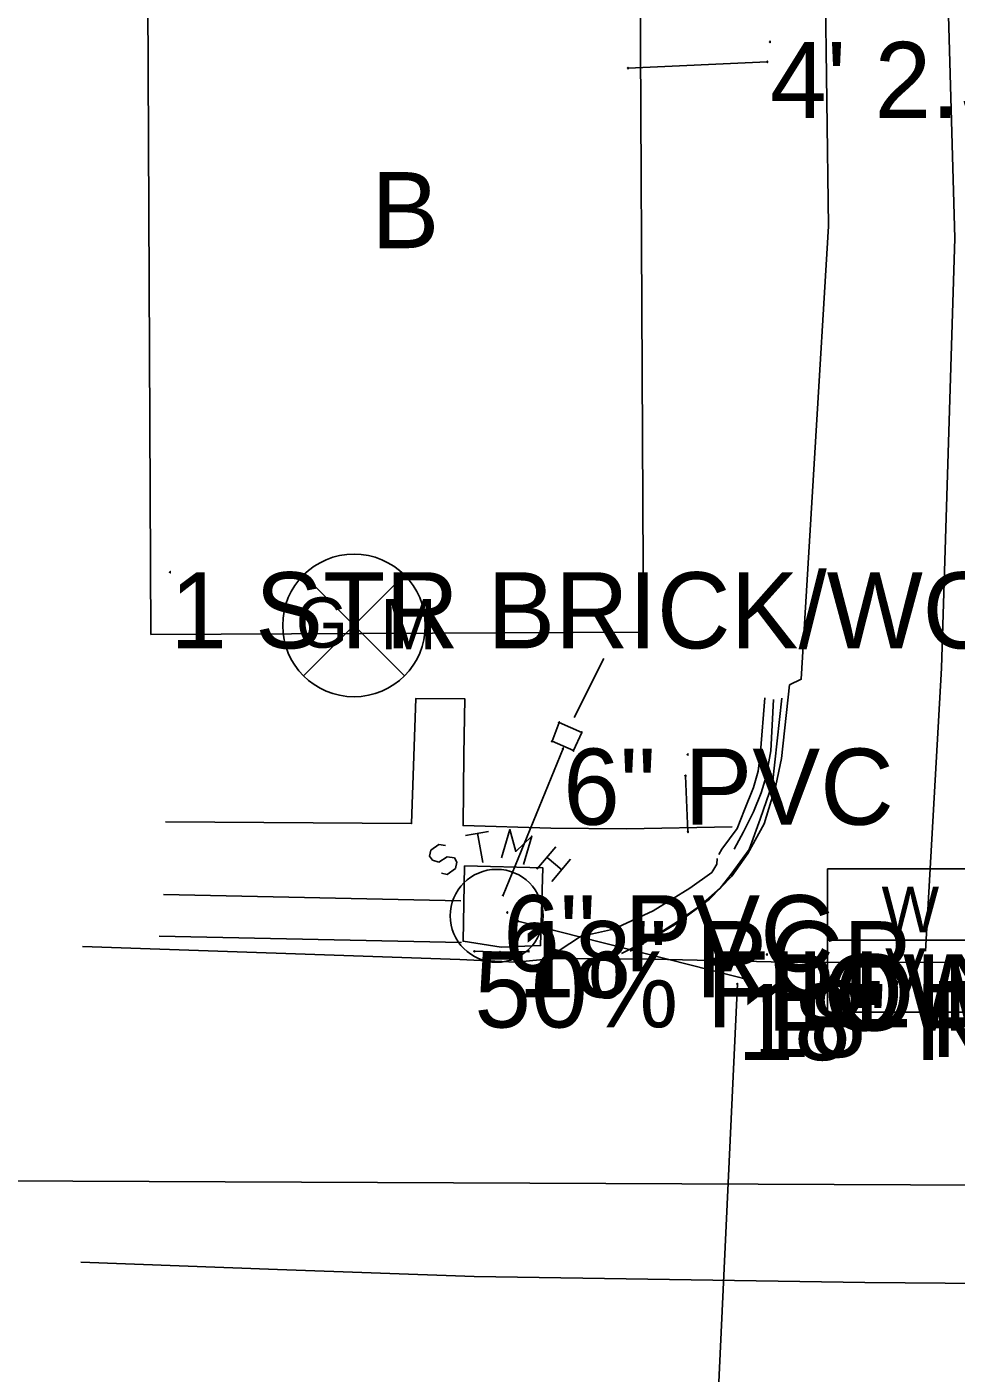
# Model space of a CAD drawing. Extents: x 1304270 to 1306561, y 1876019 to 1876752.
# Drawn here: x 1304916.1 to 1304977.1, y 1876403.7 to 1876492.1 of the extents above; entities that cross this region are included whole.
import ezdxf

# ---------------------------------------------------------------- set-up
doc = ezdxf.new("R2010")
doc.units = 0
for name, color, linetype in [('S_BUILDING', 7, 'Continuous'), ('S_BUILDING_ANNOT', 7, 'Continuous'), ('S_CATCH_BASIN', 7, 'Continuous'), ('S_CATCH_BASIN_ANNOT', 7, 'Continuous'), ('S_CURB', 7, 'Continuous'), ('S_DITCHLINE', 7, 'Continuous'), ('S_DRG_PT_SYM', 7, 'Continuous'), ('S_DROP_INLET', 7, 'Continuous'), ('S_EDGE_CONCRETE', 7, 'Continuous'), ('S_EDGE_PAVEMENT', 7, 'Continuous'), ('S_ELECTRIC_UTILITIES_ANNOT', 7, 'Continuous'), ('S_FENCE', 7, 'Continuous'), ('S_GAS_UTILITIES', 7, 'Continuous'), ('S_GATE_ANNOT', 7, 'Continuous'), ('S_MSC_PT_SYM', 7, 'Continuous'), ('S_PAVEMENT_CROWN', 7, 'Continuous'), ('S_SANITARY_SEWER', 7, 'Continuous'), ('S_SIDEWALK', 7, 'Continuous'), ('S_STORM_SEWER', 7, 'Continuous'), ('S_STORM_SEWER_ANNOT', 7, 'Continuous'), ('S_STR_PT_SYM', 7, 'Continuous'), ('S_SURVEY_TEXT_ANNOT', 7, 'Continuous'), ('S_UTL_PT_SYM', 7, 'Continuous'), ('S_WATER_UTILITIES', 7, 'Continuous')]:
    doc.layers.add(name, color=color, linetype=linetype)

msp = doc.modelspace()

# ---------------------------------------------------------------- linework, layer by layer
at = {"layer": 'S_BUILDING'}
msp.add_lwpolyline([(1304923.987, 1876507.767), (1304924.258, 1876452.214), (1304956.586, 1876452.372), (1304956.315, 1876507.925)], close=True, dxfattribs=at)
at = {"layer": 'S_CATCH_BASIN'}
for p, q in [((1304945.492, 1876431.412), (1304947.184, 1876431.359)), ((1304947.184, 1876431.359), (1304949.069, 1876431.41))]:
    msp.add_line(p, q, dxfattribs=at)
at = {"layer": 'S_CURB'}
for points in [[(1304964.549, 1876448.045), (1304964.28, 1876444.515), (1304964.13, 1876443.245), (1304963.818, 1876442.168), (1304963.225, 1876440.694), (1304962.732, 1876439.484), (1304961.738, 1876438.127), (1304961.546, 1876437.769)], [(1304924.805, 1876432.411), (1304944.655, 1876431.983)]]:
    msp.add_lwpolyline(points, dxfattribs=at)
at = {"layer": 'S_DITCHLINE'}
msp.add_lwpolyline([(1304953.99, 1876450.633), (1304952.041, 1876446.752)], dxfattribs=at)
at = {"layer": 'S_DRG_PT_SYM'}
for points in [[(1304951.062, 1876446.43), (1304951.062, 1876446.48), (1304951.062, 1876446.43), (1304951.012, 1876446.43), (1304951.062, 1876446.43), (1304951.062, 1876446.38), (1304951.062, 1876446.43), (1304951.112, 1876446.43)], [(1304952.536, 1876445.782), (1304952.536, 1876445.832), (1304952.536, 1876445.782), (1304952.486, 1876445.782), (1304952.536, 1876445.782), (1304952.536, 1876445.732), (1304952.536, 1876445.782), (1304952.586, 1876445.782)], [(1304950.595, 1876445.206), (1304950.595, 1876445.256), (1304950.595, 1876445.206), (1304950.545, 1876445.206), (1304950.595, 1876445.206), (1304950.595, 1876445.156), (1304950.595, 1876445.206), (1304950.645, 1876445.206)], [(1304952, 1876444.592), (1304952, 1876444.642), (1304952, 1876444.592), (1304951.95, 1876444.592), (1304952, 1876444.592), (1304952, 1876444.542), (1304952, 1876444.592), (1304952.05, 1876444.592)], [(1304945.492, 1876431.412), (1304945.492, 1876431.462), (1304945.492, 1876431.412), (1304945.442, 1876431.412), (1304945.492, 1876431.412), (1304945.492, 1876431.362), (1304945.492, 1876431.412), (1304945.542, 1876431.412)], [(1304947.184, 1876431.359), (1304947.184, 1876431.409), (1304947.184, 1876431.359), (1304947.134, 1876431.359), (1304947.184, 1876431.359), (1304947.184, 1876431.309), (1304947.184, 1876431.359), (1304947.234, 1876431.359)], [(1304949.069, 1876431.41), (1304949.069, 1876431.46), (1304949.069, 1876431.41), (1304949.019, 1876431.41), (1304949.069, 1876431.41), (1304949.069, 1876431.36), (1304949.069, 1876431.41), (1304949.12, 1876431.41)]]:
    msp.add_lwpolyline(points, dxfattribs=at)
at = {"layer": 'S_DROP_INLET'}
for p, q in [((1304951.062, 1876446.43), (1304950.595, 1876445.206)), ((1304952.536, 1876445.782), (1304951.062, 1876446.43)), ((1304952, 1876444.592), (1304952.536, 1876445.782)), ((1304950.595, 1876445.206), (1304952, 1876444.592))]:
    msp.add_line(p, q, dxfattribs=at)
at = {"layer": 'S_EDGE_CONCRETE'}
for points in [[(1304955.143, 1876431.273), (1304956.833, 1876432.108), (1304958.801, 1876433.34), (1304960.333, 1876434.411), (1304961.624, 1876435.566), (1304962.341, 1876436.47), (1304963.53, 1876438.087), (1304964.251, 1876440.084), (1304965.054, 1876442.428), (1304965.678, 1876448.024)], [(1304965.133, 1876447.94), (1304964.944, 1876444.58), (1304964.654, 1876442.88), (1304964.312, 1876441.821), (1304963.818, 1876440.561), (1304963.168, 1876439.246), (1304962.554, 1876438.126)], [(1304950.145, 1876431.662), (1304951.062, 1876431.474), (1304952.463, 1876432.387), (1304954.621, 1876432.867), (1304957.234, 1876434.071), (1304959.631, 1876435.549), (1304961.069, 1876436.579), (1304961.406, 1876437.144), (1304961.436, 1876437.506)]]:
    msp.add_lwpolyline(points, dxfattribs=at)
msp.add_lwpolyline([(1304944.837, 1876437.016), (1304944.749, 1876432.074), (1304947.254, 1876431.687), (1304949.84, 1876431.794), (1304949.981, 1876436.893)], close=True, dxfattribs=at)
at = {"layer": 'S_EDGE_PAVEMENT'}
for points in [[(1304955.711, 1876431.426), (1304958.857, 1876433.289), (1304960.923, 1876434.833), (1304962.396, 1876436.344), (1304963.446, 1876437.843), (1304964.523, 1876439.777), (1304965.284, 1876442.294), (1304965.646, 1876444.073), (1304966.18, 1876448.895), (1304966.95, 1876449.268), (1304967.839, 1876464.146), (1304968.728, 1876479.025), (1304968.524, 1876495.495), (1304968.319, 1876511.966), (1304968.15, 1876529.158), (1304967.981, 1876546.351), (1304968.71, 1876560.16), (1304968.788, 1876563.104)], [(1304919.779, 1876431.718), (1304944.538, 1876430.873), (1304948.222, 1876430.692), (1304950.692, 1876430.942), (1304957.212, 1876430.901), (1304966.928, 1876430.679), (1304977.139, 1876430.697), (1304984.136, 1876430.53), (1304987.418, 1876428.94), (1304989.146, 1876428.281), (1304990.755, 1876427.243), (1304997.978, 1876427.391), (1305006.508, 1876426.141), (1305007.367, 1876424.801), (1305008.544, 1876424.166), (1305009.948, 1876424.231), (1305012.143, 1876425.041), (1305027.35, 1876425.193), (1305037.635, 1876424.503)]]:
    msp.add_lwpolyline(points, dxfattribs=at)
at = {"layer": 'S_FENCE'}
msp.add_line((1304964.719, 1876489.804), (1304955.583, 1876489.39), dxfattribs=at)
msp.add_lwpolyline([(1304964.719, 1876489.804), (1304955.583, 1876489.39)], dxfattribs=at)
msp.add_lwpolyline([(1304964.719, 1876489.804), (1304955.583, 1876489.39)], dxfattribs=at)
at = {"layer": 'S_GAS_UTILITIES'}
for p, q in [((1304934.282, 1876449.497), (1304940.901, 1876456.116)), ((1304934.282, 1876456.116), (1304940.901, 1876449.497))]:
    msp.add_line(p, q, dxfattribs=at)
msp.add_circle((1304937.591, 1876452.806), 4.681, dxfattribs=at)
at = {"layer": 'S_MSC_PT_SYM'}
for points in [[(1304964.907, 1876491.11), (1304964.907, 1876491.16), (1304964.907, 1876491.11), (1304964.857, 1876491.11), (1304964.907, 1876491.11), (1304964.907, 1876491.06), (1304964.907, 1876491.11), (1304964.957, 1876491.11)], [(1304964.719, 1876489.804), (1304964.719, 1876489.854), (1304964.719, 1876489.804), (1304964.669, 1876489.804), (1304964.719, 1876489.804), (1304964.719, 1876489.754), (1304964.719, 1876489.804), (1304964.769, 1876489.804)], [(1304955.583, 1876489.39), (1304955.583, 1876489.44), (1304955.583, 1876489.39), (1304955.533, 1876489.39), (1304955.583, 1876489.39), (1304955.583, 1876489.34), (1304955.583, 1876489.39), (1304955.633, 1876489.39)], [(1304964.707, 1876431.208), (1304964.707, 1876431.258), (1304964.707, 1876431.208), (1304964.657, 1876431.208), (1304964.707, 1876431.208), (1304964.707, 1876431.158), (1304964.707, 1876431.208), (1304964.757, 1876431.208)]]:
    msp.add_lwpolyline(points, dxfattribs=at)
at = {"layer": 'S_PAVEMENT_CROWN'}
for points in [[(1304975.107, 1876431.431), (1304976.154, 1876450.009), (1304976.59, 1876464.118), (1304977.026, 1876478.228), (1304976.541, 1876495.178), (1304976.056, 1876512.129), (1304976.01, 1876528.236), (1304975.965, 1876544.344), (1304975.419, 1876558.639)], [(1304919.661, 1876411.009), (1304932.568, 1876410.532), (1304945.474, 1876410.055), (1304958.299, 1876409.86), (1304971.123, 1876409.666), (1304984.305, 1876409.563), (1304997.488, 1876409.46), (1305019.679, 1876409.408), (1305041.87, 1876409.356), (1305062.985, 1876409.225), (1305084.101, 1876409.095), (1305104.326, 1876408.423), (1305118.333, 1876408.238), (1305132.34, 1876408.054), (1305154.417, 1876408.065)]]:
    msp.add_lwpolyline(points, dxfattribs=at)
at = {"layer": 'S_SANITARY_SEWER'}
msp.add_line((1304980.649, 1876416.046), (1304699.882, 1876417.28), dxfattribs=at)
at = {"layer": 'S_SIDEWALK'}
for points in [[(1304925.215, 1876439.921), (1304941.371, 1876439.801), (1304941.64, 1876448.002), (1304944.874, 1876447.977), (1304944.797, 1876444.329), (1304944.749, 1876439.669), (1304950.515, 1876439.489), (1304955.483, 1876439.459), (1304962.416, 1876439.575)], [(1304925.08, 1876435.151), (1304944.61, 1876434.723)]]:
    msp.add_lwpolyline(points, dxfattribs=at)
at = {"layer": 'S_STORM_SEWER'}
for p, q in [((1304951.324, 1876444.721), (1304947.386, 1876435.097)), ((1304944.914, 1876439.015), (1304946.425, 1876439.286)), ((1304945.689, 1876439.17), (1304946.037, 1876437.232)), ((1304942.627, 1876438.046), (1304942.55, 1876437.659)), ((1304942.55, 1876437.659), (1304942.744, 1876437.387)), ((1304943.17, 1876438.434), (1304942.627, 1876438.046)), ((1304943.596, 1876438.356), (1304943.17, 1876438.434)), ((1304943.17, 1876437.271), (1304943.712, 1876437.62)), ((1304943.712, 1876437.62), (1304944.177, 1876437.542)), ((1304949.602, 1876436.806), (1304950.842, 1876438.279)), ((1304950.261, 1876437.581), (1304951.23, 1876436.767)), ((1304942.744, 1876437.387), (1304943.17, 1876437.271)), ((1304944.255, 1876436.845), (1304943.712, 1876436.457)), ((1304944.177, 1876437.542), (1304944.332, 1876437.271)), ((1304944.332, 1876437.271), (1304944.255, 1876436.845)), ((1304951.811, 1876437.465), (1304950.571, 1876435.992)), ((1304943.712, 1876436.457), (1304943.325, 1876436.535)), ((1304963.774, 1876429.465), (1304948.353, 1876433.392)), ((1304962.756, 1876429.271), (1304961.218, 1876396.368))]:
    msp.add_line(p, q, dxfattribs=at)
msp.add_lwpolyline([(1304948.711, 1876437.116), (1304949.254, 1876438.976), (1304948.207, 1876437.969), (1304947.82, 1876439.402), (1304947.277, 1876437.542)], dxfattribs=at)
msp.add_circle((1304946.954, 1876433.743), 3.048, dxfattribs=at)
at = {"layer": 'S_STR_PT_SYM'}
msp.add_lwpolyline([(1304925.525, 1876456.298), (1304925.525, 1876456.348), (1304925.525, 1876456.298), (1304925.475, 1876456.298), (1304925.525, 1876456.298), (1304925.525, 1876456.248), (1304925.525, 1876456.298), (1304925.575, 1876456.298)], dxfattribs=at)
at = {"layer": 'S_UTL_PT_SYM'}
for points in [[(1304951.324, 1876444.721), (1304951.324, 1876444.771), (1304951.324, 1876444.721), (1304951.274, 1876444.721), (1304951.324, 1876444.721), (1304951.324, 1876444.671), (1304951.324, 1876444.721), (1304951.374, 1876444.721)], [(1304959.507, 1876444.33), (1304959.507, 1876444.38), (1304959.507, 1876444.33), (1304959.457, 1876444.33), (1304959.507, 1876444.33), (1304959.507, 1876444.28), (1304959.507, 1876444.33), (1304959.557, 1876444.33)], [(1304959.356, 1876442.935), (1304959.356, 1876442.985), (1304959.356, 1876442.935), (1304959.306, 1876442.935), (1304959.356, 1876442.935), (1304959.356, 1876442.885), (1304959.356, 1876442.935), (1304959.406, 1876442.935)], [(1304959.512, 1876439.258), (1304959.512, 1876439.308), (1304959.512, 1876439.258), (1304959.462, 1876439.258), (1304959.512, 1876439.258), (1304959.512, 1876439.208), (1304959.512, 1876439.258), (1304959.562, 1876439.258)], [(1304947.386, 1876435.097), (1304947.386, 1876435.147), (1304947.386, 1876435.097), (1304947.336, 1876435.097), (1304947.386, 1876435.097), (1304947.386, 1876435.047), (1304947.386, 1876435.097), (1304947.436, 1876435.097)], [(1304947.656, 1876433.958), (1304947.656, 1876434.008), (1304947.656, 1876433.958), (1304947.606, 1876433.958), (1304947.656, 1876433.958), (1304947.656, 1876433.908), (1304947.656, 1876433.958), (1304947.706, 1876433.958)], [(1304948.353, 1876433.392), (1304948.353, 1876433.442), (1304948.353, 1876433.392), (1304948.303, 1876433.392), (1304948.353, 1876433.392), (1304948.353, 1876433.342), (1304948.353, 1876433.392), (1304948.403, 1876433.392)], [(1304964.706, 1876431.208), (1304964.706, 1876431.258), (1304964.706, 1876431.208), (1304964.656, 1876431.208), (1304964.706, 1876431.208), (1304964.706, 1876431.158), (1304964.706, 1876431.208), (1304964.756, 1876431.208)], [(1304962.756, 1876429.271), (1304962.756, 1876429.321), (1304962.756, 1876429.271), (1304962.706, 1876429.271), (1304962.756, 1876429.271), (1304962.756, 1876429.221), (1304962.756, 1876429.271), (1304962.806, 1876429.271)], [(1304963.774, 1876429.465), (1304963.774, 1876429.515), (1304963.774, 1876429.465), (1304963.724, 1876429.465), (1304963.774, 1876429.465), (1304963.774, 1876429.415), (1304963.774, 1876429.465), (1304963.824, 1876429.465)]]:
    msp.add_lwpolyline(points, dxfattribs=at)
at = {"layer": 'S_WATER_UTILITIES'}
for p, q in [((1304959.356, 1876442.935), (1304959.512, 1876439.258)), ((1304968.664, 1876436.824), (1304978.081, 1876436.824)), ((1304968.664, 1876427.407), (1304968.664, 1876436.824)), ((1304968.664, 1876432.135), (1304978.081, 1876432.135)), ((1304978.081, 1876427.407), (1304968.664, 1876427.407))]:
    msp.add_line(p, q, dxfattribs=at)

# ---------------------------------------------------------------- texts
at = {"layer": 'S_BUILDING_ANNOT'}
for s, p in [('B', (1304938.731, 1876477.569)), ('1 STR BRICK/WOOD', (1304925.525, 1876451.298))]:
    msp.add_text(s, height=5, dxfattribs=at).set_placement(p)
at = {"layer": 'S_CATCH_BASIN_ANNOT'}
msp.add_text('50% FILL', height=5, dxfattribs=at).set_placement((1304945.492, 1876426.412))
at = {"layer": 'S_ELECTRIC_UTILITIES_ANNOT'}
msp.add_text('POINT ON ROAD UNDER LOWES', height=5, dxfattribs=at).set_placement((1304964.706, 1876426.208))
at = {"layer": 'S_GAS_UTILITIES'}
for s, p in [('G', (1304933.772, 1876451.341)), ('M', (1304939.336, 1876451.237))]:
    msp.add_text(s, height=3.3, rotation=360, dxfattribs=at).set_placement(p)
at = {"layer": 'S_GATE_ANNOT'}
msp.add_text("4' 2.5' MTL CHAINLINK GT", height=5, dxfattribs=at).set_placement((1304964.907, 1876486.11))
at = {"layer": 'S_STORM_SEWER_ANNOT'}
for s, p in [('6" PVC', (1304951.324, 1876439.721)), ('6" PVC', (1304947.386, 1876430.097)), ('18" RCP', (1304948.353, 1876428.392)), ('18" RCP DIRECTION ONLY', (1304962.756, 1876424.271)), ('18" RCP DIRECTION ONLY', (1304963.774, 1876424.465))]:
    msp.add_text(s, height=5, dxfattribs=at).set_placement(p)
at = {"layer": 'S_SURVEY_TEXT_ANNOT'}
msp.add_text('LOWEST UTILITY LINE', height=5, dxfattribs=at).set_placement((1304964.707, 1876426.208))
at = {"layer": 'S_WATER_UTILITIES'}
for s, p in [('W', (1304972.215, 1876432.666)), ('V', (1304972.451, 1876428.603))]:
    msp.add_text(s, height=3, rotation=360, dxfattribs=at).set_placement(p)

doc.saveas('drawing.dxf')
